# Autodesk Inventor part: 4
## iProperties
Created: 2012-03
Part Number: 4
Document SubType Name: Modeling
Designer: Administrator
Density: 7.85 g/cm^3
Material: Steel
Mass: 2.49069 g
Surface Area: 4.67218 cm^2
Volume: 0.317285 cm^3
Translation Standard: STEP AP203
FileName: //expscmdclustefs.cadenas.external/client_exchange/iodir/jobs/output/wkb42693478_no0/STEP/208_9001__24208_90010__2_03.stp
PostProcessor: Build: 236a, Release: 2009 RTM - Date: Fri 02/22/2008
Sent Units: CM
Uncertainty: 0.0
Author: Administrator
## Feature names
1. Base1
